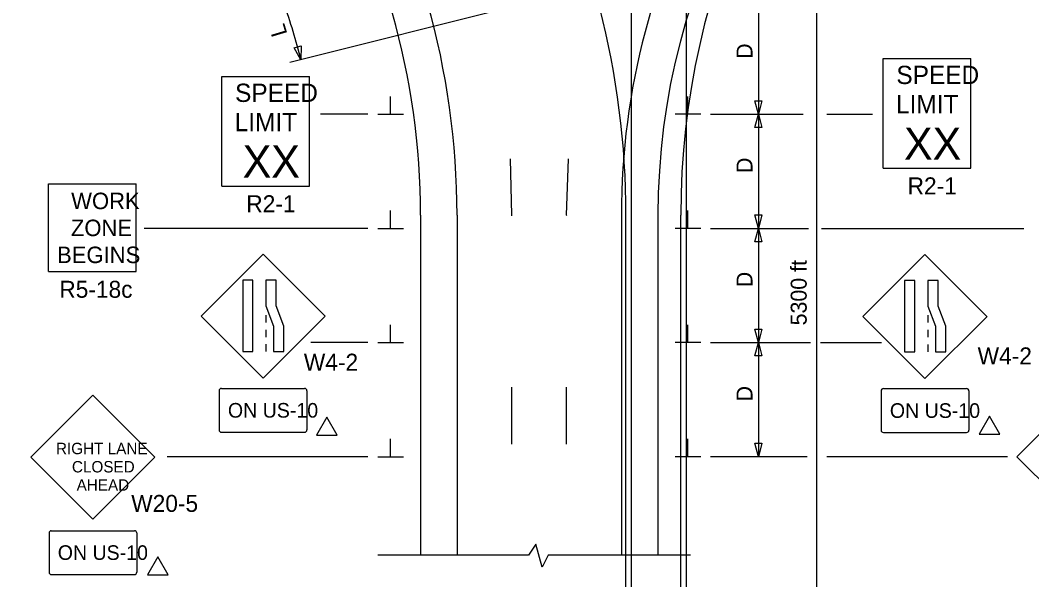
# Model space of a CAD drawing. Extents: x 16722 to 18475, y 7001 to 8243.
# Drawn here: x 16728.3 to 17171.4, y 7695.5 to 7940.5 of the extents above; entities that cross this region are included whole.
import ezdxf

# ---------------------------------------------------------------- set-up
doc = ezdxf.new("R2010")
doc.units = 0
for name, color, linetype in [('ALI_LEGAL_EX', 7, 'Continuous'), ('PAVT_EDGE_EX', 7, 'Continuous'), ('TRAFFIC_SIGNS_PR', 7, 'Continuous'), ('TYPICAL_TEXT_DIMEN_PR', 7, 'Continuous')]:
    doc.layers.add(name, color=color, linetype=linetype)

msp = doc.modelspace()

# ---------------------------------------------------------------- linework, layer by layer
at = {"layer": 'ALI_LEGAL_EX'}
for p, q in [((16995.95, 8243.16), (16995.95, 7425.02)), ((17019.95, 8243.16), (17019.95, 7425.02)), ((16993.65, 7354.84), (16993.65, 7855.19)), ((17017.65, 7354.84), (17017.65, 7855.19))]:
    msp.add_line(p, q, dxfattribs=at)
for points in [[(16943.6, 7854.85), (16943.65, 7855.19), (16943.08, 7879.84)], [(16967.7, 7854.85), (16967.65, 7855.19), (16968.48, 7879.83)], [(16943.65, 7754.84), (16943.65, 7779.84)], [(16967.65, 7754.84), (16967.65, 7779.84)]]:
    msp.add_lwpolyline(points, dxfattribs=at)
for centre, radius, start, end in [((16629.65, 7855.19), 364, 0, 57.2958), ((17357.65, 7855.19), 340, 129.5666, 180)]:
    msp.add_arc(centre, radius, start, end, dxfattribs=at)
at = {"layer": 'PAVT_EDGE_EX'}
for p, q in [((16903.65, 7855.19), (16903.65, 7706.22)), ((16919.65, 7855.19), (16919.65, 7706.22)), ((16991.65, 7855.19), (16991.65, 7706.22)), ((17007.65, 7855.19), (17007.65, 7706.22))]:
    msp.add_line(p, q, dxfattribs=at)
for centre, radius, start, end in [((16579.65, 7855.19), 340, 0, 62.6829), ((16579.65, 7855.19), 324, 0, 62.6829), ((17307.65, 7855.19), 316, 121.6214, 180), ((17307.65, 7855.19), 300, 121.6214, 180), ((17307.65, 7855.19), 300, 180, 180.00000277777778)]:
    msp.add_arc(centre, radius, start, end, dxfattribs=at)
at = {"layer": 'TRAFFIC_SIGNS_PR'}
for p, q in [((17106.34, 7923.7), (17144.74, 7923.7)), ((17106.34, 7875.7), (17106.34, 7923.7)), ((17144.74, 7875.7), (17144.74, 7923.7)), ((16816.67, 7915.87), (16855.07, 7915.87)), ((16816.67, 7867.87), (16816.67, 7915.87)), ((16855.07, 7867.87), (16855.07, 7915.87)), ((17106.34, 7875.7), (17144.74, 7875.7)), ((16740.65, 7830.41), (16740.65, 7868.81)), ((16740.65, 7868.81), (16779.05, 7868.81)), ((16779.05, 7830.41), (16779.05, 7868.81)), ((16816.67, 7867.87), (16855.07, 7867.87)), ((16834.68, 7838.06), (16807.53, 7810.91)), ((16861.84, 7810.91), (16834.68, 7838.06)), ((17124.62, 7837.96), (17097.46, 7810.8)), ((17151.77, 7810.8), (17124.62, 7837.96)), ((16740.65, 7830.41), (16779.05, 7830.41)), ((16835.93, 7811.4), (16835.93, 7808.2)), ((17125.86, 7811.29), (17125.86, 7808.09)), ((16807.53, 7810.91), (16834.68, 7783.75)), ((16834.68, 7783.75), (16861.87, 7810.94)), ((17097.46, 7810.8), (17124.62, 7783.65)), ((17124.62, 7783.65), (17151.8, 7810.84)), ((16835.93, 7805), (16835.93, 7801.8)), ((17125.86, 7804.89), (17125.86, 7801.69)), ((16835.93, 7798.6), (16835.93, 7795.4)), ((17125.86, 7798.49), (17125.86, 7795.29)), ((16760.15, 7776.29), (16733, 7749.14)), ((16787.3, 7749.14), (16760.15, 7776.29)), ((16815.46, 7778.3), (16815.46, 7761.08)), ((16816.46, 7779.3), (16852.91, 7779.3)), ((16853.91, 7778.3), (16853.91, 7761.08)), ((17105.39, 7778.2), (17105.39, 7760.98)), ((17106.39, 7779.2), (17142.84, 7779.2)), ((17143.84, 7778.2), (17143.84, 7760.98)), ((17192.02, 7776.52), (17164.87, 7749.37)), ((16816.46, 7760.08), (16852.91, 7760.08)), ((17106.39, 7759.98), (17142.84, 7759.98)), ((17164.87, 7749.37), (17192.02, 7722.23)), ((16733, 7749.14), (16760.15, 7721.99)), ((16760.15, 7721.99), (16787.3, 7749.14)), ((16740.94, 7715.99), (16740.94, 7698.79)), ((16741.94, 7716.99), (16778.35, 7716.99)), ((16779.35, 7715.99), (16779.35, 7698.79)), ((16741.94, 7697.79), (16778.35, 7697.79))]:
    msp.add_line(p, q, dxfattribs=at)
for points in [[(16825.79, 7826.64), (16825.79, 7795.4), (16830.28, 7795.4), (16830.28, 7826.64)], [(16835.93, 7826.64), (16835.93, 7815.46), (16839.27, 7806.58), (16839.27, 7795.4), (16843.76, 7795.4), (16843.76, 7806.58), (16840.42, 7815.46), (16840.42, 7826.64)], [(17115.72, 7826.54), (17115.72, 7795.29), (17120.22, 7795.29), (17120.22, 7826.54)], [(17125.86, 7826.54), (17125.86, 7815.36), (17129.2, 7806.48), (17129.2, 7795.29), (17133.7, 7795.29), (17133.7, 7806.48), (17130.35, 7815.36), (17130.35, 7826.54)]]:
    msp.add_lwpolyline(points, close=True, dxfattribs=at)
for centre, start, end in [((16816.46, 7778.3), 90, 180), ((16852.91, 7778.3), 0, 90), ((17106.39, 7778.2), 90, 180), ((17142.84, 7778.2), 0, 90), ((16816.46, 7761.08), 180, 270), ((16852.91, 7761.08), 270, 0), ((17106.39, 7760.98), 180, 270), ((17142.84, 7760.98), 270, 0), ((16741.94, 7715.99), 90, 180), ((16778.35, 7715.99), 0, 90), ((16741.94, 7698.79), 180, 270), ((16778.35, 7698.79), 270, 0)]:
    msp.add_arc(centre, 1, start, end, dxfattribs=at)
at = {"layer": 'TYPICAL_TEXT_DIMEN_PR'}
for p, q in [((17051.65, 7949.37), (17051.65, 7899.37)), ((17077.09, 7949.37), (17077.09, 7649.37)), ((16946.73, 7947.04), (16846.42, 7921.94)), ((16848.33, 7928.46), (16849.85, 7928.84)), ((16851.28, 7923.16), (16848.33, 7928.46)), ((16849.85, 7928.84), (16851.38, 7929.23)), ((16851.38, 7929.23), (16851.28, 7923.16)), ((16890.52, 7899.37), (16890.52, 7907.16)), ((17020.77, 7899.37), (17020.77, 7907.16)), ((17051.65, 7899.37), (17050.08, 7905.24)), ((17050.08, 7905.24), (17051.65, 7905.24)), ((17051.65, 7905.24), (17053.22, 7905.24)), ((17053.22, 7905.24), (17051.65, 7899.37)), ((16880.65, 7899.37), (16859.91, 7899.37)), ((16884.9, 7899.37), (16896.15, 7899.37)), ((17026.4, 7899.37), (17015.15, 7899.37)), ((17030.65, 7899.37), (17071.28, 7899.37)), ((17050.08, 7893.51), (17051.65, 7899.37)), ((17051.65, 7899.37), (17051.65, 7849.37)), ((17051.65, 7899.37), (17053.22, 7893.51)), ((17081.58, 7899.37), (17101.71, 7899.37)), ((17051.65, 7893.51), (17050.08, 7893.51)), ((17053.22, 7893.51), (17051.65, 7893.51)), ((16890.52, 7849.37), (16890.52, 7857.16)), ((17020.77, 7849.37), (17020.77, 7857.16)), ((17051.65, 7849.37), (17050.08, 7855.24)), ((17050.08, 7855.24), (17051.65, 7855.24)), ((17051.65, 7855.24), (17053.22, 7855.24)), ((17053.22, 7855.24), (17051.65, 7849.37)), ((16880.65, 7849.37), (16782.69, 7849.37)), ((16884.9, 7849.37), (16896.15, 7849.37)), ((17026.4, 7849.37), (17015.15, 7849.37)), ((17030.65, 7849.37), (17073.57, 7849.37)), ((17050.08, 7843.51), (17051.65, 7849.37)), ((17051.65, 7849.37), (17051.65, 7799.37)), ((17051.65, 7849.37), (17053.22, 7843.51)), ((17079.29, 7849.37), (17167.87, 7849.37)), ((17051.65, 7843.51), (17050.08, 7843.51)), ((17053.22, 7843.51), (17051.65, 7843.51)), ((16890.52, 7799.37), (16890.52, 7807.16)), ((17020.77, 7799.37), (17020.77, 7807.16)), ((17051.65, 7799.37), (17050.08, 7805.24)), ((17050.08, 7805.24), (17051.65, 7805.24)), ((17051.65, 7805.24), (17053.22, 7805.24)), ((17053.22, 7805.24), (17051.65, 7799.37)), ((16880.65, 7799.37), (16855.63, 7799.37)), ((16884.9, 7799.37), (16896.15, 7799.37)), ((17026.4, 7799.37), (17015.15, 7799.37)), ((17030.65, 7799.37), (17074.5, 7799.37)), ((17050.08, 7793.51), (17051.65, 7799.37)), ((17051.65, 7799.37), (17051.65, 7749.37)), ((17051.65, 7799.37), (17053.22, 7793.51)), ((17078.88, 7799.37), (17105.63, 7799.37)), ((17051.65, 7793.51), (17050.08, 7793.51)), ((17053.22, 7793.51), (17051.65, 7793.51)), ((16890.52, 7749.37), (16890.52, 7757.16)), ((17020.77, 7749.37), (17020.77, 7757.16)), ((17051.65, 7749.37), (17050.08, 7755.24)), ((17050.08, 7755.24), (17051.65, 7755.24)), ((17051.65, 7755.24), (17053.22, 7755.24)), ((17053.22, 7755.24), (17051.65, 7749.37)), ((16880.65, 7749.37), (16792.66, 7749.37)), ((16884.9, 7749.37), (16896.15, 7749.37)), ((17026.4, 7749.37), (17015.15, 7749.37)), ((17073, 7749.37), (17030.65, 7749.37)), ((17160.73, 7749.37), (17081.58, 7749.37)), ((16954.16, 7711.02), (16950.91, 7706.22)), ((16956.9, 7701.08), (16954.16, 7711.02)), ((16950.91, 7706.22), (16884.97, 7706.22)), ((16959.65, 7706.22), (16956.9, 7701.08)), ((17021.98, 7706.22), (16959.65, 7706.22))]:
    msp.add_line(p, q, dxfattribs=at)
for points in [[(17152.84, 7767.1), (17148.31, 7759.27), (17157.36, 7759.27)], [(16862.56, 7766.63), (16858.04, 7758.8), (16867.09, 7758.8)], [(16788.65, 7705.57), (16784.13, 7697.73), (16793.18, 7697.73)]]:
    msp.add_lwpolyline(points, close=True, dxfattribs=at)
msp.add_arc((16579.65, 7855.19), 280, 14.0482, 19.32, dxfattribs=at)

# ---------------------------------------------------------------- texts
at = {"layer": 'TRAFFIC_SIGNS_PR'}
for s, height, p in [('SPEED', 8, (17112.1, 7912.56)), ('SPEED', 8, (16822.44, 7904.73)), ('LIMIT', 8, (17111.94, 7899.76)), ('LIMIT', 8, (16822.28, 7891.93)), ('XX', 14.031, (17115.45, 7879.46)), ('XX', 14.031, (16825.78, 7871.63)), ('R2-1', 7.44, (17117.01, 7864.26)), ('WORK', 7.217, (16750.65, 7857.78)), ('R2-1', 7.44, (16827.35, 7856.43)), ('ZONE', 7.217, (16750.53, 7845.97)), ('BEGINS', 7.217, (16744.46, 7834.16)), ('R5-18c', 7.44, (16745.46, 7818.97)), ('W4-2', 7.449, (16852.56, 7787.04)), ('W4-2', 7.449, (17147.68, 7789.8)), ('ON US-10', 6.408, (16819.3, 7766.49)), ('ON US-10', 6.408, (17109.24, 7766.38)), ('RIGHT LANE', 4.999, (16743.99, 7750.49)), ('CLOSED', 4.999, (16750.98, 7742.49)), ('AHEAD', 4.999, (16753.03, 7734.49)), ('W20-5', 7.439, (16776.95, 7725.22)), ('ON US-10', 6.401, (16744.78, 7704.19))]:
    msp.add_text(s, height=height, dxfattribs=at).set_placement(p)
at = {"layer": 'TYPICAL_TEXT_DIMEN_PR'}
for s, rotation, p in [('L', 106.685, (16845.4, 7934.54)), ('D', 90, (17049.09, 7923.59)), ('D', 90, (17049.09, 7873.59)), ('5300 ft', 90, (17072.81, 7806.88)), ('D', 90, (17049.09, 7823.59)), ('D', 90, (17049.09, 7773.59))]:
    msp.add_text(s, height=7, rotation=rotation, dxfattribs=at).set_placement(p)

doc.saveas('drawing.dxf')
